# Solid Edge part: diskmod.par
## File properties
Author: Deepak Maini
Template: NORMENG.PAR
Last saved by: MYPC
Revision: 4
Application: Solid Edge
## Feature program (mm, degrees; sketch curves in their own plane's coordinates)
sketch for "unnamed Protrusion 1" plane through (0, 0, 0) normal (0, 0, 1) x-axis (1, 0, 0)
  line (-25.2008, 3.175) -> (-20.6375, 3.175)
  arc centre (-20.6375, 0) radius 3.175 from (-20.6375, 3.175) to (-20.6375, -3.175) cw
  line (-25.2008, -3.175) -> (-20.6375, -3.175)
  arc centre (0, 0) radius 25.4 from (-3.175, -25.2008) to (-25.2008, -3.175) cw
  line (-3.175, -25.2008) -> (-3.175, -20.6375)
  arc centre (0, -20.6375) radius 3.175 from (-3.175, -20.6375) to (3.175, -20.6375) cw
  line (3.175, -25.2008) -> (3.175, -20.6375)
  arc centre (0, 0) radius 25.4 from (25.2008, -3.175) to (3.175, -25.2008) cw
  line (25.2008, -3.175) -> (20.6375, -3.175)
  arc centre (20.6375, 0) radius 3.175 from (20.6375, -3.175) to (20.6375, 3.175) cw
  line (25.2008, 3.175) -> (20.6375, 3.175)
  arc centre (0, 0) radius 25.4 from (3.175, 25.2008) to (25.2008, 3.175) cw
  line (3.175, 25.2008) -> (3.175, 20.6375)
  arc centre (0, 20.6375) radius 3.175 from (3.175, 20.6375) to (-3.175, 20.6375) cw
  line (-3.175, 25.2008) -> (-3.175, 20.6375)
  arc centre (0, 0) radius 25.4 from (-25.2008, 3.175) to (-3.175, 25.2008) cw
extrude "unnamed Protrusion 1" add finite 3.175 along +normal
sketch for "unnamed Hole 1" plane through (0, 0, 3.175) normal (0, 0, 1) x-axis (1, 0, 0)
  hole centre (0, 0) bore radius 12.7
hole "unnamed Hole 1" through
sketch for "unnamed Protrusion 2" plane through (0, 0, 3.175) normal (0, 0, 1) x-axis (1, 0, 0)
extrude "unnamed Protrusion 2" add finite 15.875 along +normal
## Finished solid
Body 1: solid body, 22 faces, 52 edges, 32 vertices.
  Faces by surface: plane 12, cylinder 10
  Edges by curve: line 32, circle 20
Bounding box of the edges (mm): 50.402 x 50.402 x 19.050, from (-25.2008, -25.2008, 0) to (25.2008, 25.2008, 19.05).
Cylindrical faces by radius (mm): R3.175 x4, R12.7 x1, R15.3815 x1, R25.4 x4
Planar faces by outward normal: +x 2, +y 2, +z 2, -x 2, -y 2, -z 2
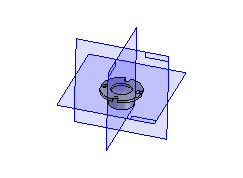
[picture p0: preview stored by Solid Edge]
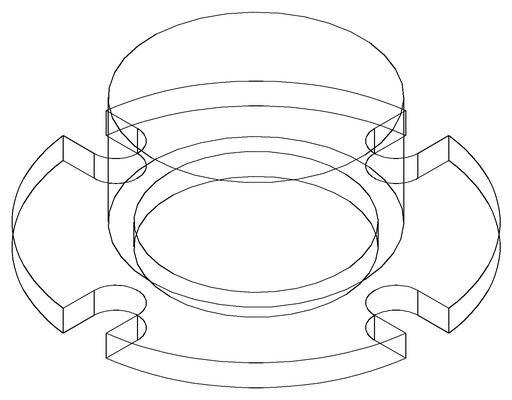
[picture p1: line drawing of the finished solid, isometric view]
